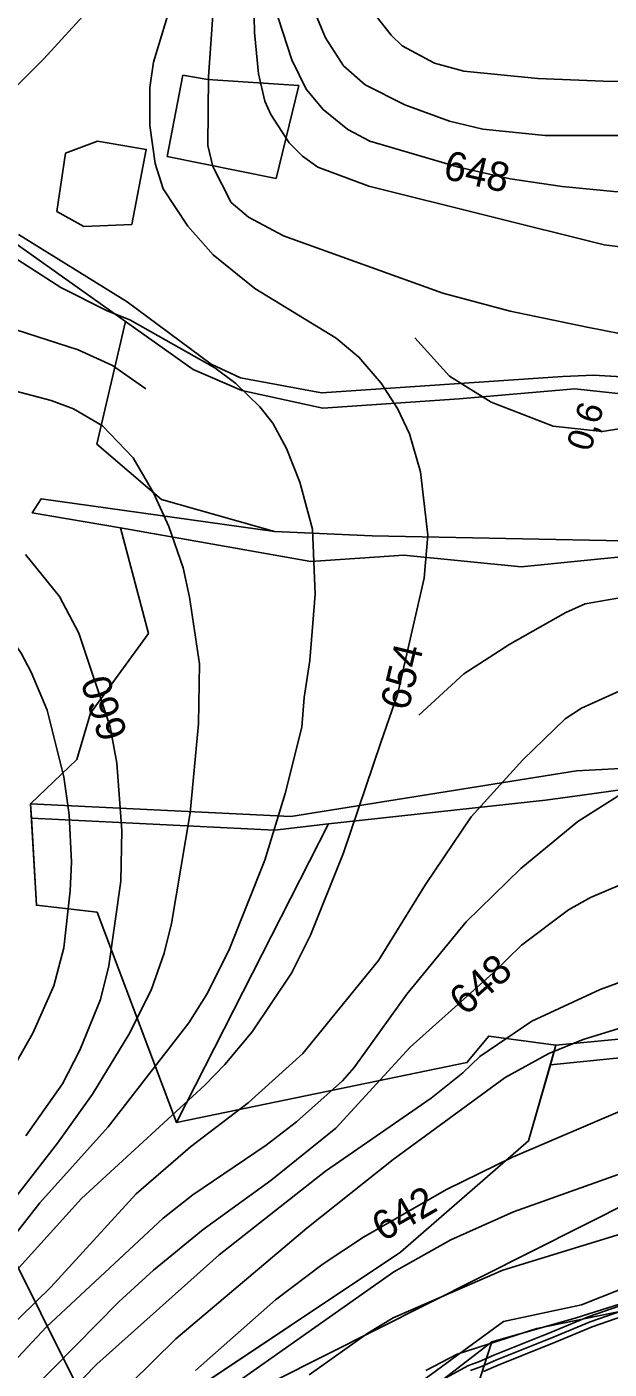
# Model space of a CAD drawing. Extents: x -709418 to -703832, y -1161719 to -1157826.
# Drawn here: x -707785.2 to -707625.6, y -1160852.4 to -1160484.5 of the extents above; entities that cross this region are included whole.
import ezdxf

# ---------------------------------------------------------------- set-up
doc = ezdxf.new("R2010")
doc.units = 0
for name, color, linetype in [('102_obvod PÚ', 7, 'Continuous'), ('120_vrstevnice hlavní', 7, 'Continuous'), ('121_vrstevnice hlavní_popis', 7, 'Continuous'), ('122_vrstevnice základní', 7, 'Continuous'), ('124_vrstevnice doplňková', 7, 'Continuous'), ('206_TTP_KN', 7, 'Continuous'), ('207_lesní pozemek_KN', 7, 'Continuous'), ('210_ostatní plocha_KN', 7, 'Continuous'), ('514 odvodnění - LPIS', 7, 'Continuous'), ('606_RBC_návrh', 7, 'Continuous'), ('717_elektronická komunikace O2', 7, 'Continuous'), ('735_OP sítí TI', 7, 'Continuous'), ('Trasa-Hlavni  staniceni', 7, 'Continuous')]:
    doc.layers.add(name, color=color, linetype=linetype)

msp = doc.modelspace()

# ---------------------------------------------------------------- linework, layer by layer
at = {"layer": '102_obvod PÚ'}
msp.add_lwpolyline([(-707760.34, -1160872.06), (-707682.79, -1160820.3), (-707647.7, -1160789.85), (-707640.18, -1160763.62), (-707658.6, -1160761.11), (-707664.56, -1160768.35), (-707744.21, -1160784.82), (-707765.98, -1160727.16), (-707782.6, -1160725.23), (-707784.19, -1160697.49), (-707771.56, -1160685.33), (-707767.81, -1160672.59), (-707751.86, -1160650.79), (-707759.55, -1160621.87), (-707783.74, -1160617.73), (-707781.32, -1160613.88), (-707717.33, -1160622.85), (-707748.33, -1160614.04), (-707765.99, -1160598.87), (-707758.16, -1160565.25), (-707791, -1160541.97)], dxfattribs=at)
at = {"layer": '120_vrstevnice hlavní'}
for points in [[(-707789.08, -1160195.94), (-707783.29, -1160207.22), (-707778.81, -1160218.5), (-707758.13, -1160278.68), (-707751.33, -1160301.24), (-707746.41, -1160323.8), (-707743.37, -1160335.09), (-707730.21, -1160376.46), (-707726.3, -1160395.26), (-707724.28, -1160417.82), (-707722.83, -1160486.09), (-707721.68, -1160497.38), (-707719.94, -1160504.9), (-707718.35, -1160508.52), (-707713.29, -1160516.32), (-707709.67, -1160519.94), (-707705.47, -1160522.98), (-707691.45, -1160528.19), (-707626.93, -1160544.24), (-707613.05, -1160545.98), (-707602.63, -1160546.27), (-707591.06, -1160545.69), (-707578.91, -1160544.1)], [(-707323.32, -1160523.99), (-707329.11, -1160546.56), (-707335.47, -1160565.36), (-707339.67, -1160572.01), (-707352.83, -1160587.78), (-707360.21, -1160594.72), (-707383.64, -1160613.96), (-707393.91, -1160621.34), (-707443.23, -1160646.07), (-707457.12, -1160651.71), (-707495.31, -1160663.57), (-707536.97, -1160674.57), (-707570.81, -1160678.18), (-707596.85, -1160683.39), (-707607.26, -1160687.15), (-707617.68, -1160691.92), (-707634.17, -1160702.34), (-707649.79, -1160715.21), (-707664.83, -1160729.82), (-707681.03, -1160749.64), (-707695.49, -1160769.74), (-707698.68, -1160773.36), (-707711.26, -1160784.64), (-707719.65, -1160791.01)], [(-707785.61, -1160629.15), (-707776.28, -1160640.65), (-707770.99, -1160650.68), (-707762.42, -1160676.36), (-707760.58, -1160686.28), (-707759.14, -1160704.8), (-707759.43, -1160718.68), (-707762.75, -1160741.83), (-707765.07, -1160751.08), (-707770.71, -1160764.97), (-707775.48, -1160774.23), (-707785.46, -1160788.4)], [(-707320.29, -1160737.78), (-707344.3, -1160746.31), (-707370.77, -1160759.62), (-707390.58, -1160772.06), (-707399.55, -1160775.24), (-707408.52, -1160776.54), (-707425.88, -1160775.67), (-707434.56, -1160774.52), (-707460.88, -1160772.49), (-707499.94, -1160770.61), (-707514.11, -1160770.47), (-707533.78, -1160771.62), (-707553.45, -1160774.66), (-707568.21, -1160778.85), (-707581.8, -1160783.48), (-707604.66, -1160792.45), (-707651.81, -1160809.23), (-707669.03, -1160816.9), (-707684.65, -1160825.72), (-707727.9, -1160856.24)], [(-707719.65, -1160791.01), (-707739.76, -1160804.6), (-707747.86, -1160810.97), (-707779.82, -1160840.76), (-707790.24, -1160851.9), (-707811.21, -1160876.06)]]:
    msp.add_lwpolyline(points, dxfattribs=at)
at = {"layer": '122_vrstevnice základní'}
for points in [[(-707787.49, -1160215.03), (-707774.47, -1160250.04), (-707767.53, -1160272.31), (-707761.31, -1160289.67), (-707755.38, -1160310.79), (-707745.25, -1160355.05), (-707738.89, -1160373.27), (-707734.26, -1160388.89), (-707731.8, -1160401.91), (-707730.79, -1160412.33), (-707732.67, -1160459.19), (-707735.42, -1160498.25), (-707735.56, -1160517.05), (-707734.26, -1160522.83), (-707729.2, -1160532.67), (-707724.42, -1160536.72), (-707714.88, -1160541.78), (-707671.2, -1160557.55), (-707652.68, -1160562.47), (-707631.62, -1160566.85), (-707622.31, -1160568.69), (-707604.95, -1160570.13), (-707588.46, -1160569.12)], [(-707789.37, -1160230.65), (-707780.11, -1160253.8), (-707774.76, -1160271.15), (-707766.08, -1160299.5), (-707762.9, -1160309.92), (-707744.1, -1160385.42), (-707743.08, -1160393.23), (-707739.34, -1160424.32), (-707738.45, -1160442.12), (-707740.62, -1160459.48), (-707742.07, -1160466.42), (-707750.46, -1160494.2), (-707751.47, -1160501.14), (-707751.47, -1160511.55), (-707750.03, -1160521.97), (-707747.86, -1160528.91), (-707741.06, -1160539.18), (-707734.11, -1160546.99), (-707722.69, -1160556.25), (-707700.41, -1160569.84)], [(-707791.68, -1160504.47), (-707780.55, -1160493.33), (-707767.82, -1160479.44), (-707760.3, -1160468.16), (-707757.11, -1160462.08), (-707753.21, -1160451.96), (-707750.46, -1160441.83), (-707748.72, -1160423.61), (-707748.29, -1160404.37), (-707754.08, -1160375.01), (-707759.43, -1160355.92), (-707768.69, -1160317.73), (-707778.67, -1160279.54), (-707782.72, -1160266.81), (-707792.7, -1160241.94)], [(-707701.71, -1160449.65), (-707696.07, -1160469.61), (-707692.02, -1160478.28), (-707685.37, -1160486.82), (-707682.33, -1160489.71), (-707673.51, -1160494.48), (-707665.41, -1160496.65), (-707645.16, -1160498.68), (-707624.91, -1160499.55), (-707616.23, -1160499.26), (-707606.97, -1160498.1), (-707597.72, -1160496.22), (-707575.87, -1160487.54), (-707560.4, -1160478.86), (-707543.04, -1160466.86), (-707526.26, -1160453.84), (-707504.58, -1160433.29), (-707492.48, -1160420.08), (-707487.79, -1160414.35), (-707479.97, -1160403.94), (-707474.91, -1160396.13), (-707462.47, -1160377.03), (-707461.32, -1160375.3), (-707456.92, -1160369.1)], [(-707488.22, -1160456.88), (-707511.07, -1160485.66), (-707518.45, -1160492.6), (-707528.14, -1160500.41), (-707540.58, -1160509.24), (-707548.83, -1160513.87), (-707566.62, -1160521.1), (-707582.67, -1160525.73), (-707604.08, -1160529.05), (-707616.23, -1160529.78), (-707624.33, -1160529.63), (-707638.51, -1160528.33), (-707652.68, -1160526.16), (-707666.85, -1160522.98), (-707691.16, -1160515.89), (-707697.23, -1160512.71), (-707704.03, -1160507.21), (-707708.66, -1160501.57), (-707712.56, -1160493.62), (-707716.32, -1160482.05)], [(-707536.1, -1160484.36), (-707547.09, -1160491.74), (-707564.01, -1160501.28), (-707580.65, -1160508.23), (-707592.8, -1160511.26), (-707604.37, -1160513), (-707618.26, -1160514.3), (-707643.13, -1160514.3), (-707660.2, -1160512.56), (-707669.31, -1160510.4), (-707681.61, -1160505.91), (-707692.46, -1160500.42), (-707698.39, -1160495.21), (-707703.31, -1160487.54), (-707706.34, -1160480.31)], [(-707733.68, -1160577.94), (-707756.97, -1160564.78), (-707763.19, -1160562.32), (-707775.92, -1160555.96), (-707791.83, -1160545.69)], [(-707700.41, -1160569.84), (-707694.19, -1160575.05), (-707688.12, -1160582.14), (-707683.63, -1160589.08), (-707680.31, -1160596.03), (-707677.27, -1160606.44), (-707675.32, -1160623.86), (-707676.33, -1160635.6), (-707683.63, -1160667.48), (-707688.19, -1160680.65), (-707698.39, -1160710.87), (-707707.5, -1160733.44), (-707712.71, -1160743.85), (-707723.41, -1160759.91), (-707730.93, -1160768.88), (-707736.43, -1160774.52), (-707770.28, -1160805.61), (-707804.56, -1160843.51), (-707826.4, -1160870.13)], [(-707841.3, -1160881.78), (-707815.69, -1160848.14), (-707795.73, -1160824.71), (-707781.7, -1160806.77), (-707762.9, -1160785.94), (-707740.77, -1160757.45), (-707735.71, -1160749.35), (-707729.63, -1160737.2), (-707719.94, -1160712.9), (-707714.44, -1160694.67), (-707709.81, -1160676.45), (-707709.24, -1160668.35), (-707707.65, -1160658.22), (-707706.2, -1160640), (-707706.92, -1160622.21), (-707710.39, -1160609.33), (-707714.01, -1160600.07), (-707717.77, -1160593.13), (-707721.39, -1160588.65), (-707727.9, -1160582.28), (-707733.68, -1160577.94)], [(-707788.65, -1160584.31), (-707778.52, -1160586.91), (-707772.45, -1160589.23), (-707764.49, -1160593.85), (-707756.1, -1160602.68), (-707750.46, -1160612.23), (-707746.27, -1160621.48), (-707742.36, -1160632.76), (-707740.62, -1160640.86), (-707737.88, -1160659.09), (-707738.17, -1160675.58), (-707740.48, -1160699.88), (-707745.54, -1160730.26), (-707747.57, -1160738.35), (-707751.18, -1160748.48), (-707757.26, -1160760.63), (-707767.24, -1160776.98), (-707776.79, -1160790.43), (-707792.26, -1160810.39)], [(-707847.66, -1160618.16), (-707833.49, -1160621.34), (-707821.67, -1160625.45), (-707812.6, -1160629.46), (-707812.37, -1160630.31), (-707803.69, -1160636.24), (-707792.98, -1160647.37), (-707786.77, -1160656.2), (-707784.02, -1160661.4), (-707779.68, -1160671.82), (-707775.05, -1160690.04), (-707773.6, -1160700.46), (-707773.02, -1160713.48), (-707773.31, -1160721.29), (-707775.05, -1160736.91), (-707777.8, -1160747.32), (-707783.58, -1160760.34), (-707790.96, -1160773.36), (-707797.61, -1160783.77), (-707830.16, -1160830.06), (-707869.79, -1160883)], [(-707665.7, -1160771.19), (-707661.07, -1160766.71), (-707646.75, -1160757.01), (-707628.09, -1160748.33), (-707598.44, -1160737.49), (-707563.29, -1160727.94), (-707551.72, -1160725.34), (-707540.15, -1160723.75), (-707499.65, -1160721.72), (-707473.61, -1160719.41), (-707456.25, -1160716.37), (-707441.79, -1160711.88), (-707425.59, -1160705.38), (-707411.7, -1160697.42), (-707395.07, -1160685.27), (-707371.64, -1160669.36), (-707357.32, -1160661.11), (-707334.32, -1160645.35), (-707325.21, -1160637.1)], [(-707581.8, -1160657.79), (-707603.79, -1160661.11), (-707621.82, -1160666.13), (-707633.17, -1160671.27), (-707637.64, -1160674.13), (-707649.21, -1160685.42), (-707663.38, -1160701.04), (-707675.97, -1160719.55), (-707688.84, -1160740.38), (-707709.53, -1160765.84), (-707724.57, -1160779.43), (-707740.34, -1160791.44), (-707755.23, -1160804.31), (-707778.67, -1160829.92), (-707791.25, -1160842.21), (-707805.14, -1160857.11)], [(-707315.37, -1160665.16), (-707351.82, -1160690.04), (-707369.76, -1160699.88), (-707405.19, -1160717.09), (-707422.7, -1160727.65), (-707434.7, -1160734.02), (-707447.29, -1160739.22), (-707461.17, -1160742.98), (-707471.59, -1160744.43), (-707496.75, -1160744.86), (-707510.64, -1160743.56), (-707530.6, -1160744.29), (-707543.62, -1160746.46), (-707578.62, -1160748.62), (-707597.72, -1160751.23), (-707632.72, -1160762.08), (-707642.12, -1160765.84), (-707654.13, -1160772.49), (-707684.79, -1160794.91), (-707708.51, -1160813.71), (-707744.39, -1160844.09), (-707763.04, -1160862.46)], [(-707783.87, -1160858.12), (-707760.01, -1160833.97), (-707750.46, -1160825.29), (-707736.86, -1160814.15), (-707718.35, -1160800.7), (-707700.56, -1160786.38), (-707680.16, -1160764.1), (-707657.45, -1160743.85), (-707649.64, -1160736.19), (-707636.77, -1160726.49), (-707630.69, -1160723.17), (-707614.78, -1160716.37), (-707598.87, -1160711.16), (-707576.6, -1160705.09), (-707554.32, -1160700.89), (-707518.16, -1160697.28), (-707483.45, -1160691.64), (-707469.56, -1160688.02)], [(-707739.03, -1160852.77), (-707717.05, -1160833.39), (-707704.03, -1160823.55), (-707692.89, -1160816.17), (-707670.18, -1160803.16), (-707652.1, -1160794.33), (-707621.29, -1160781.17), (-707610.3, -1160775.38), (-707593.09, -1160769.45), (-707579.49, -1160764.1), (-707570.81, -1160761.64), (-707556.35, -1160758.89), (-707536.1, -1160756.87), (-707510.06, -1160756.15), (-707481.42, -1160758.03), (-707460.59, -1160761.21)], [(-707315.95, -1160767.43), (-707338.8, -1160775.38), (-707348.06, -1160779.72), (-707357.32, -1160785.22), (-707373.52, -1160793.03), (-707382.77, -1160796.21), (-707396.66, -1160799.83), (-707412.86, -1160801.42), (-707426.75, -1160802), (-707449.89, -1160799.97), (-707475.35, -1160795.63), (-707498.49, -1160793.03), (-707527.13, -1160793.18), (-707553.17, -1160797.66), (-707571.39, -1160802.14), (-707592.22, -1160808.36), (-707622.31, -1160815.31), (-707654.71, -1160825.29), (-707684.79, -1160838.3), (-707691.73, -1160842.5), (-707707.79, -1160853.93)], [(-707777.22, -1160862.46), (-707766.08, -1160851.03), (-707732.52, -1160821.09), (-707703.31, -1160798.09), (-707674.38, -1160778.13), (-707665.7, -1160771.19)], [(-707675.82, -1160852.77), (-707667.29, -1160848.28), (-707645.45, -1160841.2), (-707600.9, -1160832.08), (-707585.57, -1160827.89), (-707560.69, -1160819.93), (-707545.07, -1160816.17), (-707527.71, -1160815.02), (-707519.61, -1160815.16), (-707495.89, -1160819.07), (-707482.87, -1160821.81), (-707472.45, -1160824.71), (-707462.04, -1160826.44), (-707451.62, -1160827.46), (-707433.4, -1160828.9), (-707411.7, -1160829.48), (-707403.02, -1160828.9), (-707379.3, -1160825.14), (-707357.03, -1160819.5), (-707335.33, -1160811.69), (-707311.61, -1160799.68)]]:
    msp.add_lwpolyline(points, dxfattribs=at)
at = {"layer": '124_vrstevnice doplňková'}
for points in [[(-707870.02, -1160567.12), (-707849.09, -1160563.2), (-707831.46, -1160561.89), (-707818.44, -1160562.47), (-707804.85, -1160564.06), (-707790.96, -1160566.66), (-707771.14, -1160573.03), (-707761.74, -1160577.36), (-707752.63, -1160583.73)], [(-707678.89, -1160569.79), (-707669.31, -1160580.26), (-707657.89, -1160587.35), (-707640.96, -1160594), (-707627.51, -1160595.45), (-707616.52, -1160593.71), (-707606.97, -1160590.96), (-707597.43, -1160587.35), (-707581.08, -1160579.54)], [(-707677.79, -1160673.12), (-707665.43, -1160661.87), (-707652.83, -1160653.74), (-707637.49, -1160645.06), (-707632.12, -1160642.63), (-707623.75, -1160641.15), (-707617.68, -1160640.29), (-707607.26, -1160640.86), (-707589.9, -1160646.79), (-707582.82, -1160648.68)]]:
    msp.add_lwpolyline(points, dxfattribs=at)
at = {"layer": '206_TTP_KN'}
for p, q in [((-707765.99, -1160598.87), (-707758.16, -1160565.25)), ((-707758.16, -1160565.25), (-707739.66, -1160578.44)), ((-707739.66, -1160578.44), (-707726.24, -1160584.22)), ((-707726.24, -1160584.22), (-707704.05, -1160589.01)), ((-707666.66, -1160586.44), (-707634.97, -1160583.73)), ((-707634.97, -1160583.73), (-707605.79, -1160586.94)), ((-707704.05, -1160589.01), (-707666.66, -1160586.44)), ((-707748.33, -1160614.04), (-707765.99, -1160598.87)), ((-707717.33, -1160622.85), (-707748.33, -1160614.04)), ((-707751.86, -1160650.79), (-707759.55, -1160621.87)), ((-707759.55, -1160621.87), (-707707.4, -1160631.02)), ((-707690.55, -1160624.03), (-707717.33, -1160622.85)), ((-707611.93, -1160625.57), (-707690.55, -1160624.03)), ((-707707.4, -1160631.02), (-707681.86, -1160629.27)), ((-707681.86, -1160629.27), (-707649.67, -1160632.52)), ((-707631.55, -1160630.73), (-707623.2, -1160629.84)), ((-707649.67, -1160632.52), (-707631.55, -1160630.73)), ((-707767.81, -1160672.59), (-707751.86, -1160650.79)), ((-707771.56, -1160685.33), (-707767.81, -1160672.59)), ((-707784.19, -1160697.49), (-707771.56, -1160685.33)), ((-707634.51, -1160688.39), (-707712.88, -1160700.93)), ((-707612.1, -1160687.25), (-707634.51, -1160688.39)), ((-707633.02, -1160695.06), (-707612.25, -1160692.14)), ((-707643.04, -1160696.49), (-707633.02, -1160695.06)), ((-707712.88, -1160700.93), (-707784.19, -1160697.49)), ((-707702.56, -1160702.91), (-707643.04, -1160696.49)), ((-707783.97, -1160701.37), (-707717.33, -1160704.66)), ((-707782.6, -1160725.23), (-707783.97, -1160701.37)), ((-707702.56, -1160702.91), (-707744.21, -1160784.82)), ((-707744.21, -1160784.82), (-707702.56, -1160702.91)), ((-707717.33, -1160704.66), (-707702.56, -1160702.91)), ((-707765.98, -1160727.16), (-707782.6, -1160725.23)), ((-707744.21, -1160784.82), (-707765.98, -1160727.16)), ((-707555.84, -1160755.54), (-707640.18, -1160763.62)), ((-707658.6, -1160761.11), (-707664.56, -1160768.35)), ((-707640.18, -1160763.62), (-707658.6, -1160761.11)), ((-707641.71, -1160768.95), (-707557.05, -1160760.38)), ((-707664.56, -1160768.35), (-707744.21, -1160784.82)), ((-707647.7, -1160789.85), (-707641.71, -1160768.95)), ((-707682.79, -1160820.3), (-707647.7, -1160789.85)), ((-707760.34, -1160872.06), (-707682.79, -1160820.3)), ((-707607.84, -1160824.67), (-707633.18, -1160834.73)), ((-707634.91, -1160838.43), (-707608.43, -1160830.04)), ((-707633.18, -1160834.73), (-707654.58, -1160839.3)), ((-707654.58, -1160839.3), (-707689.69, -1160864.99)), ((-707657.78, -1160844.85), (-707634.91, -1160838.43)), ((-707672.66, -1160890.98), (-707657.78, -1160844.85))]:
    msp.add_line(p, q, dxfattribs=at)
for points in [[(-707833.35, -1160458.63), (-707761.13, -1160453.89), (-707744.29, -1160461.35), (-707731.77, -1160475.83), (-707692.56, -1160475.65), (-707678.57, -1160476.69), (-707654.79, -1160478.81), (-707622.18, -1160481.06), (-707558.65, -1160485.36), (-707558.76, -1160539.48), (-707565.18, -1160544.41), (-707589.59, -1160546.4), (-707590.3, -1160555.25), (-707585.38, -1160560.25), (-707593.3, -1160574.66), (-707603.58, -1160581.51), (-707629.91, -1160580.01), (-707638.33, -1160580.37), (-707704.48, -1160584.87), (-707726.67, -1160580.73), (-707734.66, -1160576.95), (-707757.71, -1160559.89), (-707787.54, -1160541.48)], [(-707746.72, -1160520.07), (-707716.89, -1160526.05), (-707710.69, -1160500.64), (-707735.61, -1160498.94), (-707742.44, -1160497.78), (-707746.72, -1160520.07)], [(-707777.01, -1160535.14), (-707769.58, -1160539.28), (-707756.48, -1160538.68), (-707752.49, -1160518.12), (-707765.81, -1160515.88), (-707774.58, -1160519.13), (-707777.01, -1160535.14)]]:
    msp.add_lwpolyline(points, dxfattribs=at)
at = {"layer": '207_lesní pozemek_KN'}
for p, q in [((-707746.72, -1160520.07), (-707742.44, -1160497.78)), ((-707742.44, -1160497.78), (-707735.61, -1160498.94)), ((-707735.61, -1160498.94), (-707710.69, -1160500.64)), ((-707710.69, -1160500.64), (-707716.89, -1160526.05)), ((-707716.89, -1160526.05), (-707746.72, -1160520.07)), ((-707783.74, -1160617.73), (-707781.32, -1160613.88)), ((-707781.32, -1160613.88), (-707717.33, -1160622.85)), ((-707759.55, -1160621.87), (-707783.74, -1160617.73)), ((-707707.4, -1160631.02), (-707759.55, -1160621.87)), ((-707717.33, -1160622.85), (-707690.55, -1160624.03)), ((-707690.55, -1160624.03), (-707611.93, -1160625.57)), ((-707681.86, -1160629.27), (-707707.4, -1160631.02)), ((-707649.67, -1160632.52), (-707681.86, -1160629.27)), ((-707623.2, -1160629.84), (-707631.55, -1160630.73)), ((-707631.55, -1160630.73), (-707649.67, -1160632.52))]:
    msp.add_line(p, q, dxfattribs=at)
at = {"layer": '210_ostatní plocha_KN'}
for p, q in [((-707774.58, -1160519.13), (-707765.81, -1160515.88)), ((-707765.81, -1160515.88), (-707752.49, -1160518.12)), ((-707777.01, -1160535.14), (-707774.58, -1160519.13)), ((-707752.49, -1160518.12), (-707756.48, -1160538.68)), ((-707769.58, -1160539.28), (-707777.01, -1160535.14)), ((-707787.54, -1160541.48), (-707757.71, -1160559.89)), ((-707756.48, -1160538.68), (-707769.58, -1160539.28)), ((-707758.16, -1160565.25), (-707791, -1160541.97)), ((-707757.71, -1160559.89), (-707734.66, -1160576.95)), ((-707739.66, -1160578.44), (-707758.16, -1160565.25)), ((-707726.24, -1160584.22), (-707739.66, -1160578.44)), ((-707734.66, -1160576.95), (-707726.67, -1160580.73)), ((-707726.67, -1160580.73), (-707704.48, -1160584.87)), ((-707704.48, -1160584.87), (-707638.33, -1160580.37)), ((-707638.33, -1160580.37), (-707629.91, -1160580.01)), ((-707629.91, -1160580.01), (-707603.58, -1160581.51)), ((-707704.05, -1160589.01), (-707726.24, -1160584.22)), ((-707634.97, -1160583.73), (-707666.66, -1160586.44)), ((-707605.79, -1160586.94), (-707634.97, -1160583.73)), ((-707666.66, -1160586.44), (-707704.05, -1160589.01)), ((-707712.88, -1160700.93), (-707634.51, -1160688.39)), ((-707634.51, -1160688.39), (-707612.1, -1160687.25)), ((-707612.25, -1160692.14), (-707633.02, -1160695.06)), ((-707633.02, -1160695.06), (-707643.04, -1160696.49)), ((-707784.19, -1160697.49), (-707712.88, -1160700.93)), ((-707783.97, -1160701.37), (-707784.19, -1160697.49)), ((-707643.04, -1160696.49), (-707702.56, -1160702.91)), ((-707717.33, -1160704.66), (-707783.97, -1160701.37)), ((-707702.56, -1160702.91), (-707717.33, -1160704.66)), ((-707640.18, -1160763.62), (-707555.84, -1160755.54)), ((-707557.05, -1160760.38), (-707641.71, -1160768.95)), ((-707641.71, -1160768.95), (-707640.18, -1160763.62)), ((-707633.18, -1160834.73), (-707607.84, -1160824.67)), ((-707608.43, -1160830.04), (-707634.91, -1160838.43)), ((-707654.58, -1160839.3), (-707633.18, -1160834.73)), ((-707689.69, -1160864.99), (-707654.58, -1160839.3)), ((-707634.91, -1160838.43), (-707657.78, -1160844.85)), ((-707657.78, -1160844.85), (-707691.07, -1160870.54)), ((-707691.07, -1160870.54), (-707657.78, -1160844.85)), ((-707657.78, -1160844.85), (-707672.66, -1160890.98))]:
    msp.add_line(p, q, dxfattribs=at)
at = {"layer": '514 odvodnění - LPIS'}
msp.add_lwpolyline([(-707426.72, -1160922.44), (-707441.87, -1160997.91), (-707476.65, -1160997.1), (-707492.95, -1160963.95), (-707513.5, -1160966.37), (-707570.68, -1160996.42), (-707577.66, -1160964.63), (-707595.13, -1160969.2), (-707612.03, -1161048.56), (-707698.98, -1160915.4), (-707745.87, -1160869.91), (-707562.29, -1160777.61), (-707485.01, -1160770.42), (-707423.61, -1160786.68), (-707402.42, -1160806.85), (-707379.79, -1160825.66)], close=True, dxfattribs=at)
at = {"layer": '606_RBC_návrh'}
msp.add_lwpolyline([(-708110.78, -1161332.9), (-708059.34, -1161283.11), (-707938.43, -1161304.2), (-707908.41, -1161301.76), (-707886.5, -1161283.92), (-707849.17, -1161233.63), (-707845.12, -1161151.72), (-707839.44, -1161099), (-707814.28, -1161034.92), (-707778.58, -1160957.06), (-707727.46, -1160891.36), (-707760.73, -1160878.38), (-707802.11, -1160795.65), (-707878.77, -1160695.3), (-707928.27, -1160649.07), (-707987.5, -1160626.36), (-708046.73, -1160614.19), (-708048.36, -1160536.33), (-708135.18, -1160482.8), (-708179, -1160478.74), (-708234.99, -1160497.4)], dxfattribs=at)
at = {"layer": '717_elektronická komunikace O2'}
msp.add_lwpolyline([(-707622.11, -1160836.38), (-707630.82, -1160839.42), (-707641.73, -1160843.97), (-707643.44, -1160844.64), (-707656.62, -1160849.93), (-707660.54, -1160851.65), (-707663.58, -1160852.72)], dxfattribs=at)
at = {"layer": '735_OP sítí TI'}
for points in [[(-707622.67, -1160834.99), (-707631.36, -1160838.02), (-707642.29, -1160842.58), (-707643.99, -1160843.25), (-707657.2, -1160848.55), (-707661.09, -1160850.25), (-707664.19, -1160851.35), (-707673.37, -1160856.39)], [(-707621.55, -1160837.77), (-707630.28, -1160840.82), (-707641.17, -1160845.36), (-707642.89, -1160846.03), (-707656.04, -1160851.31), (-707659.99, -1160853.05)]]:
    msp.add_lwpolyline(points, dxfattribs=at)

# ---------------------------------------------------------------- texts
at = {"layer": '121_vrstevnice hlavní_popis'}
for s, rotation, p in [('648', 347.1007, (-707671.4, -1160526.05)), ('654', 76.5027, (-707680.65, -1160672.18)), ('660', 107.6906, (-707757.52, -1160678.53)), ('648', 41.3949, (-707664.98, -1160755.78)), ('642', 29.8609, (-707687.62, -1160817.6))]:
    msp.add_text(s, height=8, rotation=rotation, dxfattribs=at).set_placement(p)
at = {"layer": 'Trasa-Hlavni  staniceni'}
for height, p in [(0.000000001, (-707625.64, -1160574.87)), (7, (-707630.72, -1160601.21))]:
    msp.add_text('0,6', height=height, rotation=73.0347, dxfattribs=at).set_placement(p)

doc.saveas('drawing.dxf')
